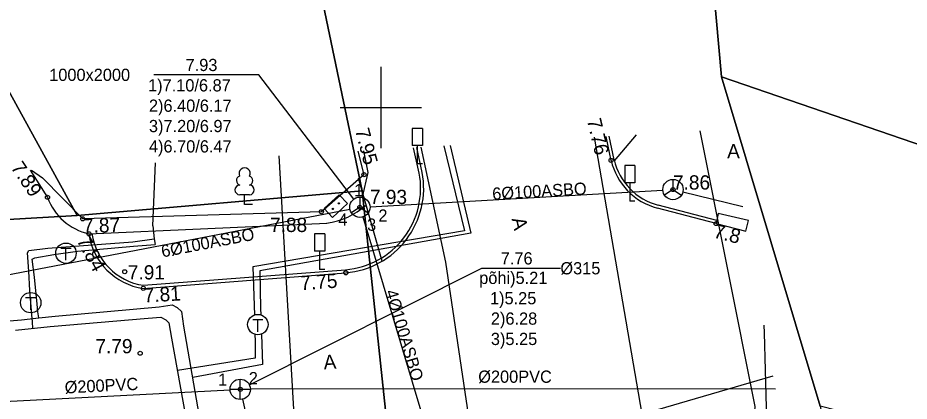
# Model space of a CAD drawing. Extents: x 473307 to 473719, y 6532843 to 6533381.
# Drawn here: x 473582.18 to 473625.94, y 6533285.57 to 6533304.4 of the extents above; entities that cross this region are included whole.
import ezdxf

# ---------------------------------------------------------------- set-up
doc = ezdxf.new("R2010")
doc.units = 0
for name, color, linetype in [('AED', 7, 'Continuous'), ('Default', 7, 'Continuous'), ('KORGUS', 7, 'Continuous'), ('KPKAABEL', 7, 'Continuous'), ('KTRASS', 7, 'Continuous'), ('LIIKLUS', 7, 'Continuous'), ('MPKAABEL', 7, 'Continuous'), ('PIIR', 7, 'Continuous'), ('POST', 7, 'Continuous'), ('PUU', 7, 'Continuous'), ('SIKAEV', 7, 'Continuous'), ('SIKAEV_NR', 7, 'Continuous'), ('SITRASS', 7, 'Continuous'), ('SITRASS_TEKST', 7, 'Continuous'), ('SKKAEV', 7, 'Continuous'), ('SKKAEV_NR', 7, 'Continuous'), ('SKTRASS', 7, 'Continuous'), ('SKTRASS_TEKST', 7, 'Continuous'), ('TEE', 7, 'Continuous'), ('TKAEV', 7, 'Continuous'), ('TTRASS', 7, 'Continuous'), ('VORK', 7, 'Continuous'), ('VTRASS', 7, 'Continuous')]:
    doc.layers.add(name, color=color, linetype=linetype)

# ---------------------------------------------------------------- blocks, each defined once
blk = doc.blocks.new('SIKAEV')
at = {"layer": 'Default'}
for p, q in [((0, 1), (0, 0)), ((0, 0), (-0.83, -0.55)), ((0, 0), (0.83, -0.55))]:
    blk.add_line(p, q, dxfattribs=at)
blk.add_circle((0, 0), 1, dxfattribs=at)
blk = doc.blocks.new('LEHTP1')
at = {"layer": 'Default'}
for p, q in [((0.48, 0.95), (-0.48, 0.95)), ((0, 0), (0, 0.95)), ((0.76, 0), (0, 0))]:
    blk.add_line(p, q, dxfattribs=at)
for centre, radius, start, end in [((0, 3.04), 0.554, 332.5799, 207.4201), ((-0.34, 2.345), 0.465, 109.02174, 253.14154), ((0.34, 2.345), 0.465, 286.85082, 70.98591), ((-0.475, 1.425), 0.475, 90.0016, 269.3953), ((0.475, 1.425), 0.475, 270.6047, 89.9984)]:
    blk.add_arc(centre, radius, start, end, dxfattribs=at)
blk = doc.blocks.new('SOKAEV')
at = {"layer": 'Default'}
for p, q in [((-0.5, 0.5), (0.5, 0.5)), ((0, -0.7), (0, 0.5))]:
    blk.add_line(p, q, dxfattribs=at)
blk.add_circle((0, 0), 1, dxfattribs=at)
blk = doc.blocks.new('LIIKLM')
at = {"layer": 'Default'}
for points in [[(-0.5, 3.5), (-0.5, 1.8)], [(0.5, 3.5), (-0.5, 3.5)], [(0.5, 3.5), (0.5, 1.8)], [(0.5, 1.8), (-0.5, 1.8)], [(0, 1.8), (0, 0)], [(0.5, 0), (0, 0)]]:
    blk.add_lwpolyline(points, dxfattribs=at)
blk = doc.blocks.new('KAKAEV')
at = {"layer": 'Default'}
for p, q in [((0, -1), (0, 1)), ((-1, 0), (1, 0))]:
    blk.add_line(p, q, dxfattribs=at)
blk.add_circle((0, 0), 1, dxfattribs=at)
blk = doc.blocks.new('SIKAPP')
at = {"layer": 'Default'}
blk.add_lwpolyline([(-1, 0.6), (1, 0.6), (1, -0.6), (-1, -0.6)], close=True, dxfattribs=at)
for centre, radius in [((-0.4, 0), 0.0608), ((-0.4, 0), 0.0581), ((-0.4, 0), 0.0553), ((-0.4, 0), 0.0526), ((-0.4, 0), 0.0499), ((-0.4, 0), 0.0472), ((-0.4, 0), 0.0444), ((-0.4, 0), 0.0417), ((-0.4, 0), 0.039), ((-0.4, 0), 0.0363), ((-0.4, 0), 0.0335), ((-0.4, 0), 0.0308), ((-0.4, 0), 0.0281), ((-0.4, 0), 0.0254), ((-0.4, 0), 0.0226), ((-0.4, 0), 0.0199), ((-0.4, 0), 0.0172), ((-0.4, 0), 0.0145), ((-0.4, 0), 0.0117), ((-0.4, 0), 0.00902), ((-0.4, 0), 0.0063), ((-0.4, 0), 0.00358), ((-0.4, 0), 0.000852), ((0.4, 0), 0.0608), ((0.4, 0), 0.0581), ((0.4, 0), 0.0553), ((0.4, 0), 0.0526), ((0.4, 0), 0.0499), ((0.4, 0), 0.0472), ((0.4, 0), 0.0444), ((0.4, 0), 0.0417), ((0.4, 0), 0.039), ((0.4, 0), 0.0363), ((0.4, 0), 0.0335), ((0.4, 0), 0.0308), ((0.4, 0), 0.0281), ((0.4, 0), 0.0254), ((0.4, 0), 0.0226), ((0.4, 0), 0.0199), ((0.4, 0), 0.0172), ((0.4, 0), 0.0145), ((0.4, 0), 0.0117), ((0.4, 0), 0.00902), ((0.4, 0), 0.0063), ((0.4, 0), 0.00358), ((0.4, 0), 0.000852)]:
    blk.add_circle(centre, radius, dxfattribs=at)
blk = doc.blocks.new('VKORIS')
at = {"layer": 'Default'}
for p, q in [((0, 4), (0, -4)), ((-4, 0), (4, 0))]:
    blk.add_line(p, q, dxfattribs=at)

msp = doc.modelspace()

# ---------------------------------------------------------------- linework, layer by layer
at = {"layer": 'AED'}
msp.add_line((473582.844, 6533296.919), (473583.385, 6533296.536), dxfattribs=at)
msp.add_lwpolyline([(473598.866, 6533297.859), (473599.172, 6533296.697), (473597.082, 6533294.876), (473585.366, 6533294.53), (473583.385, 6533296.536)], dxfattribs=at)
at = {"layer": 'KORGUS'}
for centre in [(473611.303, 6533297.399), (473599.172, 6533296.697), (473583.635, 6533295.584), (473614.342, 6533295.967), (473597.082, 6533294.876), (473598.971, 6533295.099), (473585.366, 6533294.53), (473616.464, 6533294.295), (473585.672, 6533293.793), (473587.429, 6533291.93), (473598.283, 6533291.878), (473588.338, 6533291.113), (473588.187, 6533287.924), (473593.099, 6533286.154)]:
    msp.add_circle(centre, 0.1, dxfattribs=at)
at = {"layer": 'KPKAABEL'}
msp.add_lwpolyline([(473615.664, 6533298.845), (473618.359, 6533285.308), (473618.229, 6533283.689), (473616.939, 6533282.082), (473615.155, 6533281.15), (473604.958, 6533279.899), (473594.081, 6533279.705), (473584.872, 6533279.168), (473575.551, 6533278.541), (473567.551, 6533277.966), (473562.423, 6533278.215), (473560.662, 6533279.216), (473558.752, 6533280.739), (473548.282, 6533291.71), (473546.684, 6533294.796)], dxfattribs=at)
at = {"layer": 'KTRASS'}
msp.add_lwpolyline([(473594.985, 6533297.631), (473596.263, 6533275.544)], dxfattribs=at)
at = {"layer": 'MPKAABEL'}
for points in [[(473620.191, 6533259.447), (473620.669, 6533261.927), (473620.008, 6533272.193), (473619.024, 6533281.587), (473618.831, 6533288.933), (473618.813, 6533289.306)], [(473636.059, 6533169.782), (473634.239, 6533181.673), (473632.606, 6533189.833), (473631.267, 6533197.327), (473629.932, 6533205.197), (473627.365, 6533217.651), (473628.02, 6533220.588), (473626.187, 6533228.162), (473625.63, 6533235.006), (473624.395, 6533236.238), (473625.088, 6533237.039), (473624.62, 6533240.685), (473623.001, 6533248.826), (473621.554, 6533256.337), (473620.191, 6533259.447), (473620.669, 6533261.927), (473620.008, 6533272.193), (473619.024, 6533281.587), (473618.831, 6533288.933), (473618.813, 6533289.306)]]:
    msp.add_lwpolyline(points, dxfattribs=at)
at = {"layer": 'PIIR'}
for points in [[(473546.848, 6533380.885), (473548.67, 6533377.72), (473552.06, 6533377.52), (473554.47, 6533373.83), (473554.77, 6533368.87), (473546.99, 6533364.16), (473553.35, 6533352.46), (473569.29, 6533323.48), (473585.1, 6533294.7), (473545.58, 6533292.4), (473536.31, 6533310.52), (473520.75, 6533316.46), (473504.35, 6533345.55), (473500.43, 6533353.19), (473502.79, 6533354.42), (473513.31, 6533359.89), (473507.16, 6533371.28), (473506.33, 6533372.83), (473521.647, 6533380.885)], [(473678.608, 6532842.593), (473677.66, 6532847.73), (473668.24, 6532906.4), (473664.64, 6532927.81), (473654.16, 6532926.37), (473630.89, 6533065.72), (473641.36, 6533067.51), (473636.3, 6533097.55), (473618.8, 6533170.64), (473609.94, 6533222.84), (473601.54, 6533272.81), (473599.09, 6533295.91), (473592.3, 6533328.43), (473587.14, 6533353.72), (473584.47, 6533353.28), (473580.56, 6533374.06), (473585.23, 6533374.14), (473584.699, 6533380.885)], [(473609.342, 6533380.885), (473610.48, 6533371.09), (473616.72, 6533301.5), (473621.56, 6533285.32), (473637.37, 6533201.6), (473653.19, 6533109.36), (473652.55, 6533109.39), (473658.35, 6533068.44), (473658.1, 6533064.14), (473666.14, 6533015.71), (473666.15, 6533015.71), (473680.29, 6532930.36), (473685.16, 6532910.71), (473685.75, 6532908.33), (473689.51, 6532885.44), (473695.16, 6532852.24), (473696.267, 6532845.502)], [(473718.698, 6533261.006), (473709.47, 6533263.27), (473669.64, 6533273.05), (473621.56, 6533285.32), (473616.72, 6533301.5), (473664.88, 6533284.96), (473718.698, 6533271.662)], [(473306.698, 6533269.314), (473318.22, 6533273.04), (473319.15, 6533273.32), (473325.84, 6533274.58), (473345.31, 6533277.99), (473387.78, 6533284.78), (473409.45, 6533285.94), (473429.73, 6533289.19), (473430.17, 6533286.8), (473480.73, 6533288.66), (473545.58, 6533292.4), (473585.1, 6533294.7), (473599.09, 6533295.91), (473601.54, 6533272.81), (473586.5, 6533271.93), (473496.37, 6533266.79), (473372.23, 6533259.41), (473356.5, 6533258.46), (473354.97, 6533266.17), (473326.61, 6533261.28), (473306.698, 6533254.866)]]:
    msp.add_lwpolyline(points, dxfattribs=at)
for points in [[(473643.33, 6533371.87), (473644.47, 6533364.79), (473657.67, 6533366.55), (473659.65, 6533365.77), (473664.88, 6533284.96), (473616.72, 6533301.5), (473610.48, 6533371.09)], [(473569.29, 6533323.48), (473592.3, 6533328.43), (473599.09, 6533295.91), (473585.1, 6533294.7)]]:
    msp.add_lwpolyline(points, close=True, dxfattribs=at)
at = {"layer": 'SIKAEV_NR'}
msp.add_lwpolyline([(473598.668, 6533295.496), (473594.013, 6533301.602), (473588.858, 6533301.602)], dxfattribs=at)
at = {"layer": 'SITRASS'}
msp.add_line((473614.828, 6533295.848), (473617.766, 6533295.133), dxfattribs=at)
for points in [[(473599.141, 6533297.875), (473599.364, 6533296.804), (473599.083, 6533295.586)], [(473606.492, 6533270.158), (473603.192, 6533292.394), (473601.985, 6533298.042)], [(473599.471, 6533295.113), (473613.843, 6533295.938)], [(473579.948, 6533291.448), (473598.48, 6533295.005)], [(473599.114, 6533294.62), (473606.423, 6533270.143)]]:
    msp.add_lwpolyline(points, dxfattribs=at)
at = {"layer": 'SKKAEV_NR'}
msp.add_lwpolyline([(473593.546, 6533286.378), (473604.96, 6533292.101), (473608.815, 6533292.101)], dxfattribs=at)
at = {"layer": 'SKTRASS'}
for points in [[(473558.997, 6533284.4), (473592.599, 6533286.129)], [(473593.597, 6533286.201), (473619.374, 6533286.184)], [(473593.207, 6533285.666), (473595.739, 6533274.217)]]:
    msp.add_lwpolyline(points, dxfattribs=at)
at = {"layer": 'TEE'}
for points in [[(473611.303, 6533297.399), (473611.056, 6533298.574)], [(473611.303, 6533297.399), (473611.056, 6533298.574)], [(473611.449, 6533297.431), (473611.207, 6533298.583)], [(473612.54, 6533298.662), (473611.458, 6533297.384)], [(473612.54, 6533298.662), (473611.458, 6533297.384)], [(473601.884, 6533296.779), (473601.61, 6533298.02)], [(473602.031, 6533296.809), (473601.761, 6533298.029)], [(473582.777, 6533296.915), (473583.635, 6533295.584)], [(473600.061, 6533292.447), (473598.896, 6533296.532)], [(473616.464, 6533294.295), (473613.583, 6533295.053)], [(473616.502, 6533294.44), (473613.621, 6533295.198)], [(473617.92, 6533293.928), (473618.042, 6533294.444), (473616.561, 6533294.798), (473616.464, 6533294.295), (473617.92, 6533293.928)], [(473585.672, 6533293.793), (473597.341, 6533294.315)], [(473588.338, 6533291.113), (473598.283, 6533291.878)], [(473588.343, 6533291.264), (473598.271, 6533292.028)]]:
    msp.add_lwpolyline(points, dxfattribs=at)
for centre, radius, start, end in [((473614.389, 6533298.118), 3.019, 193.136, 255.2594), ((473614.389, 6533298.118), 3.169, 193.1058, 255.2594), ((473597.932, 6533296.035), 4.022, 274.8354, 10.6636), ((473597.932, 6533296.035), 4.172, 274.8275, 10.6963), ((473586.296, 6533296.557), 2.833, 200.0763, 257.2777), ((473596.829, 6533297.993), 3.714, 277.9188, 311.2159), ((473588.781, 6533294.22), 3.139, 187.8204, 261.8795), ((473588.781, 6533294.22), 2.989, 187.8204, 261.5679)]:
    msp.add_arc(centre, radius, start, end, dxfattribs=at)
at = {"layer": 'TTRASS'}
for points in [[(473603.087, 6533298.107), (473604.1, 6533293.938), (473593.722, 6533292.17), (473593.794, 6533289.804)], [(473603.41, 6533298.126), (473604.411, 6533293.819), (473594.052, 6533291.974), (473594.092, 6533290.131), (473594.092, 6533290.131), (473594.103, 6533289.813)], [(473588.812, 6533294.19), (473588.943, 6533297.277)], [(473588.812, 6533294.19), (473588.875, 6533293.539), (473588.915, 6533293.271)], [(473582.912, 6533289.143), (473582.904, 6533289.472), (473582.87, 6533289.812), (473582.771, 6533291.001), (473582.724, 6533291.954), (473582.661, 6533292.865), (473582.727, 6533292.971), (473583.656, 6533293.095), (473587.822, 6533293.4), (473588.875, 6533293.539)], [(473583.209, 6533289.664), (473583.163, 6533289.968), (473583.131, 6533290.345), (473583, 6533291.658), (473582.889, 6533292.546), (473583.017, 6533292.618), (473583.948, 6533292.773), (473585.114, 6533292.936), (473587.855, 6533293.181), (473588.915, 6533293.271)], [(473581.571, 6533289.506), (473582.357, 6533289.56), (473583.209, 6533289.664), (473584.017, 6533289.75), (473589.111, 6533290.209), (473589.756, 6533290.303), (473590.004, 6533290.177), (473590.22, 6533289.978), (473590.314, 6533289.259), (473591.775, 6533280.853), (473592.002, 6533279.644), (473592.11, 6533279.072), (473592.288, 6533277.816), (473592.297, 6533277.757)], [(473582.064, 6533289.054), (473583.759, 6533289.232), (473588.581, 6533289.646), (473589.192, 6533289.706), (473589.443, 6533289.57), (473589.585, 6533289.426), (473589.727, 6533288.668), (473591.303, 6533279.848), (473591.551, 6533278.61), (473591.655, 6533278.091), (473591.775, 6533277.426)], [(473593.822, 6533288.853), (473593.832, 6533288.536), (473593.832, 6533288.536), (473593.826, 6533287.681), (473590.011, 6533287.073)], [(473594.135, 6533288.864), (473594.185, 6533287.372), (473590.776, 6533286.741)]]:
    msp.add_lwpolyline(points, dxfattribs=at)
at = {"layer": 'VTRASS'}
for points in [[(473610.467, 6533298.54), (473612.816, 6533284.928), (473621.946, 6533241.242), (473627.014, 6533212.114), (473627.084, 6533211.254), (473634.761, 6533160.18), (473647.035, 6533084.422), (473650.297, 6533065.838)], [(473612.816, 6533284.928), (473619.259, 6533286.823)]]:
    msp.add_lwpolyline(points, dxfattribs=at)

# ---------------------------------------------------------------- block references
at = {"layer": 'LIIKLUS', "xscale": 0.5, "yscale": 0.5}
for p in [(473601.791, 6533297.223), (473612.221, 6533295.394), (473596.996, 6533292.036)]:
    msp.add_blockref('LIIKLM', p, dxfattribs=at)
at = {"layer": 'POST', "xscale": 0.5000000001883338, "yscale": 0.5, "rotation": 43.02993274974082}
msp.add_blockref('SIKAPP', (473597.791, 6533295.153), dxfattribs=at)
at = {"layer": 'PUU', "xscale": 0.5, "yscale": 0.5}
msp.add_blockref('LEHTP1', (473593.313, 6533295.237), dxfattribs=at)
at = {"layer": 'SIKAEV', "xscale": 0.5, "yscale": 0.5}
for p in [(473614.342, 6533295.967), (473598.971, 6533295.099)]:
    msp.add_blockref('SIKAEV', p, dxfattribs=at)
at = {"layer": 'SKKAEV', "xscale": 0.5, "yscale": 0.5}
msp.add_blockref('KAKAEV', (473593.099, 6533286.154), dxfattribs=at)
at = {"layer": 'TKAEV', "xscale": 0.5, "yscale": 0.5}
for p in [(473584.543, 6533292.841), (473582.811, 6533290.411), (473593.962, 6533289.334)]:
    msp.add_blockref('SOKAEV', p, dxfattribs=at)
at = {"layer": 'VORK', "xscale": 0.5, "yscale": 0.5}
msp.add_blockref('VKORIS', (473600, 6533300), dxfattribs=at)

# ---------------------------------------------------------------- texts
at = {"layer": 'KORGUS'}
for s, rotation, p in [('7.76', 283.3755, (473610.113, 6533299.377)), ('7.95', 284.7478, (473598.73, 6533298.886)), ('7.89', 303.8575, (473581.809, 6533297.049)), ('7.87', 1.6916, (473585.387, 6533293.83)), ('7.8', 345.6847, (473616.291, 6533293.617)), ('7.84', 297.9995, (473585.054, 6533293.464)), ('7.75', 3.9676, (473596.07, 6533291.023)), ('7.81', 3.3754, (473588.379, 6533290.414))]:
    msp.add_text(s, height=0.7, rotation=rotation, dxfattribs=at).set_placement(p)
for s, p in [('7.86', (473614.342, 6533295.967)), ('7.93', (473599.465, 6533295.256)), ('7.88', (473594.561, 6533293.881)), ('7.91', (473587.58, 6533291.551)), ('7.79', (473585.987, 6533287.924))]:
    msp.add_text(s, height=0.7, dxfattribs=at).set_placement(p)
at = {"layer": 'SIKAEV_NR'}
for s, p in [('7.93', (473590.416, 6533301.787)), ('1000x2000', (473583.72, 6533301.302)), ('1)7.10/6.87', (473588.573, 6533300.787)), ('2)6.40/6.17', (473588.616, 6533299.787)), ('3)7.20/6.97', (473588.616, 6533298.787)), ('4)6.70/6.47', (473588.616, 6533297.787)), ('1', (473598.687, 6533295.636)), ('4', (473597.917, 6533294.193)), ('2', (473599.879, 6533294.389)), ('3', (473599.325, 6533293.943))]:
    msp.add_text(s, height=0.6, dxfattribs=at).set_placement(p)
at = {"layer": 'SITRASS_TEKST'}
for s, rotation, p in [('6%%c100ASBO', 3.2868, (473605.487, 6533295.458)), ('6%%c100ASBO', 10.8645, (473589.278, 6533292.628)), ('4%%c100ASBO', 286.6247, (473600.209, 6533290.954))]:
    msp.add_text(s, height=0.6, rotation=rotation, dxfattribs=at).set_placement(p)
at = {"layer": 'SKKAEV_NR'}
for s, p in [('7.76', (473605.888, 6533292.288)), ('%%c315', (473608.815, 6533291.801)), ('põhi)5.21', (473604.83, 6533291.329)), ('1)5.25', (473605.359, 6533290.329)), ('2)6.28', (473605.402, 6533289.329)), ('3)5.25', (473605.402, 6533288.329)), ('1', (473592.012, 6533286.327)), ('2', (473593.518, 6533286.404))]:
    msp.add_text(s, height=0.6, dxfattribs=at).set_placement(p)
at = {"layer": 'SKTRASS_TEKST'}
for rotation, p in [(359.962, (473604.782, 6533286.477)), (2.8631, (473584.494, 6533285.949))]:
    msp.add_text('%%c200PVC', height=0.6, rotation=rotation, dxfattribs=at).set_placement(p)
at = {"layer": 'TEE'}
msp.add_text('A', height=0.7, dxfattribs=at).set_placement((473617, 6533297.501))
for rotation, p in [(282.8493, (473606.416, 6533294.526)), (3.6175, (473597.208, 6533287.131))]:
    msp.add_text('A', height=0.7, rotation=rotation, dxfattribs=at).set_placement(p)

doc.saveas('drawing.dxf')
